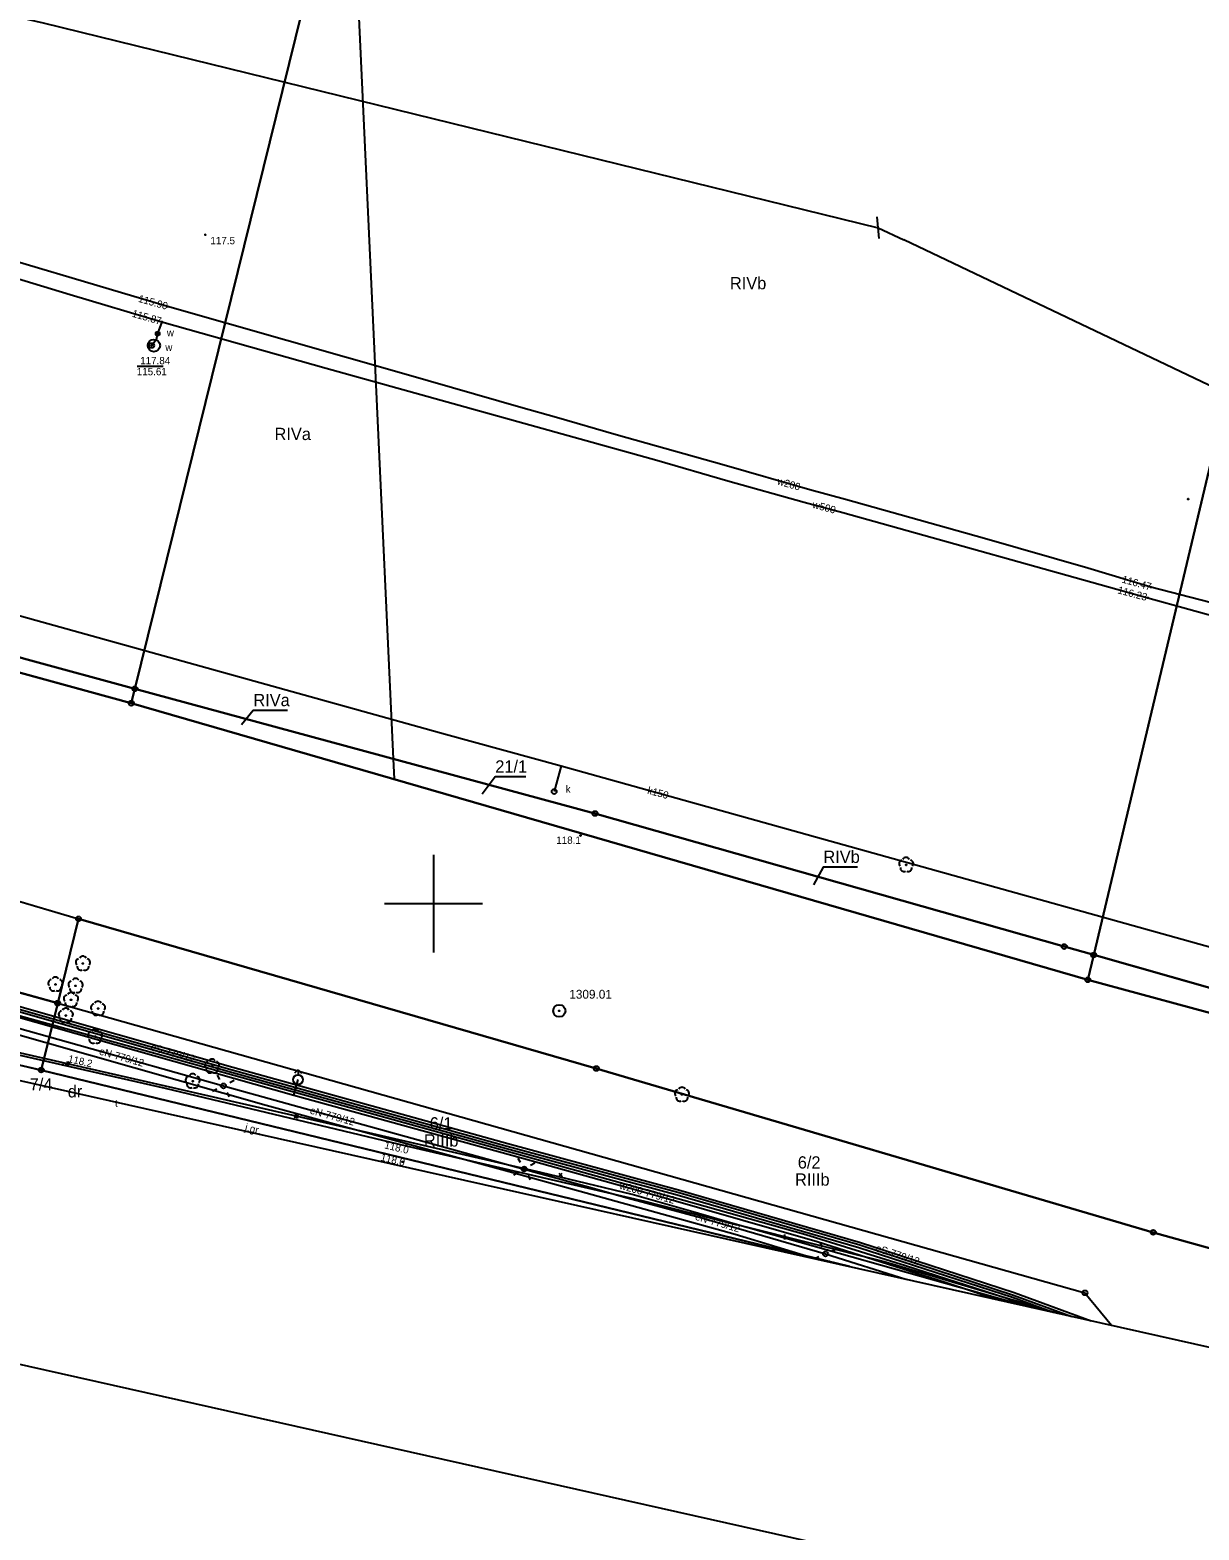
# Model space of a CAD drawing. Extents: x 6424617 to 6425697, y 5665845 to 5667190.
# Drawn here: x 6424958.8 to 6425078.2, y 5665936 to 5666089.2 of the extents above; entities that cross this region are included whole.
import ezdxf

# ---------------------------------------------------------------- set-up
doc = ezdxf.new("R2010")
doc.units = 0
for name, color, linetype in [('Warstwa 1', 7, 'Continuous'), ('Warstwa 10', 7, 'Continuous'), ('Warstwa 11', 7, 'Continuous'), ('Warstwa 12', 7, 'Continuous'), ('Warstwa 13', 7, 'Continuous'), ('Warstwa 14', 7, 'Continuous'), ('Warstwa 15', 7, 'Continuous'), ('Warstwa 16', 7, 'Continuous'), ('Warstwa 2', 7, 'Continuous'), ('Warstwa 21', 7, 'Continuous'), ('Warstwa 3', 7, 'Continuous'), ('Warstwa 4', 7, 'Continuous'), ('Warstwa 5', 7, 'Continuous'), ('Warstwa 6', 7, 'Continuous'), ('Warstwa 62', 7, 'Continuous'), ('Warstwa 63', 7, 'Continuous'), ('Warstwa 8', 7, 'Continuous')]:
    doc.layers.add(name, color=color, linetype=linetype)

msp = doc.modelspace()

# ---------------------------------------------------------------- linework, layer by layer
at = {"layer": 'Warstwa 1'}
for p, q in [((6425067.43, 5665994.76), (6425095.62, 5666113.43)), ((6425067.43, 5665994.76), (6425095.62, 5666113.43)), ((6424969.49, 5666021.95), (6424991.14, 5666109.69)), ((6424969.49, 5666021.95), (6424991.14, 5666109.69)), ((6424991.46, 5666109.7), (6424995.88, 5666014.79)), ((6424991.46, 5666109.7), (6424995.88, 5666014.79)), ((6424835.72, 5666057.05), (6424969.12, 5666020.47)), ((6424835.72, 5666057.05), (6424969.12, 5666020.47)), ((6424958.47, 5666024.93), (6424969.49, 5666021.95)), ((6424958.47, 5666024.93), (6424969.49, 5666021.95)), ((6424969.12, 5666020.47), (6424969.49, 5666021.95)), ((6424969.12, 5666020.47), (6424969.49, 5666021.95)), ((6424969.49, 5666021.95), (6424995.88, 5666014.79)), ((6424969.49, 5666021.95), (6424995.88, 5666014.79)), ((6424969.12, 5666020.47), (6424995.97, 5666012.71)), ((6424969.12, 5666020.47), (6425066.83, 5665992.22)), ((6424995.88, 5666014.79), (6424995.97, 5666012.71)), ((6424995.88, 5666014.79), (6425016.48, 5666009.21)), ((6424995.88, 5666014.79), (6424995.97, 5666012.71)), ((6424995.88, 5666014.79), (6425016.48, 5666009.21)), ((6424995.97, 5666012.71), (6425066.83, 5665992.22)), ((6424890.46, 5666009.6), (6424961.6, 5665989.83)), ((6424890.46, 5666009.6), (6424961.6, 5665989.83)), ((6425016.48, 5666009.21), (6425064.42, 5665995.62)), ((6425016.48, 5666009.21), (6425064.42, 5665995.62)), ((6424934.12, 5666007.2), (6424963.73, 5665998.45)), ((6424934.12, 5666007.2), (6424963.73, 5665998.45)), ((6424885.54, 5666000.14), (6424959.92, 5665983.01)), ((6424885.54, 5666000.14), (6424959.92, 5665983.01)), ((6424961.6, 5665989.83), (6424963.73, 5665998.45)), ((6424961.6, 5665989.83), (6424963.73, 5665998.45)), ((6424963.73, 5665998.45), (6425016.62, 5665983.17)), ((6424963.73, 5665998.45), (6425016.62, 5665983.17)), ((6425064.42, 5665995.62), (6425067.43, 5665994.76)), ((6425064.42, 5665995.62), (6425067.43, 5665994.76)), ((6425066.83, 5665992.22), (6425067.43, 5665994.76)), ((6425066.83, 5665992.22), (6425067.43, 5665994.76)), ((6425067.43, 5665994.76), (6425114.83, 5665981.3)), ((6425067.43, 5665994.76), (6425114.83, 5665981.3)), ((6425066.83, 5665992.22), (6425114.34, 5665979.37)), ((6425066.83, 5665992.22), (6425114.34, 5665979.37)), ((6424959.92, 5665983.01), (6424961.6, 5665989.83)), ((6424959.92, 5665983.01), (6424961.6, 5665989.83)), ((6424961.6, 5665989.83), (6425066.54, 5665960.25)), ((6424961.6, 5665989.83), (6425066.54, 5665960.25)), ((6424959.92, 5665983.01), (6425042.51, 5665962.94)), ((6424959.92, 5665983.01), (6425042.51, 5665962.94)), ((6425016.62, 5665983.17), (6425073.51, 5665966.43)), ((6425016.62, 5665983.17), (6425073.51, 5665966.43)), ((6425073.51, 5665966.43), (6425123.83, 5665952.42)), ((6425073.51, 5665966.43), (6425123.83, 5665952.42)), ((6425066.54, 5665960.25), (6425069.25, 5665956.94)), ((6425066.54, 5665960.25), (6425069.25, 5665956.94))]:
    msp.add_line(p, q, dxfattribs=at)
at = {"layer": 'Warstwa 10'}
msp.add_lwpolyline([(6425060.44, 5665958.92), (6425057.61, 5665959.71), (6425030.82, 5665967.28), (6425026.23, 5665968.58), (6425020.29, 5665970.3), (6425010.94, 5665972.53), (6424974.55, 5665980.91), (6424952.41, 5665985.97)], dxfattribs=at)
for centre in [(6424969.49, 5666021.95), (6424969.12, 5666020.47), (6424969.12, 5666020.47), (6425016.48, 5666009.21), (6424963.73, 5665998.45), (6425064.42, 5665995.62), (6425067.43, 5665994.76), (6425066.83, 5665992.22), (6425066.83, 5665992.22), (6424961.6, 5665989.83), (6424959.92, 5665983.01), (6425016.62, 5665983.17), (6425073.51, 5665966.43), (6425066.54, 5665960.25)]:
    msp.add_circle(centre, 0.25, dxfattribs=at)
at = {"layer": 'Warstwa 11'}
for centre in [(6425048.27, 5666003.96), (6424964.18, 5665993.89), (6424961.37, 5665991.76), (6424963.43, 5665991.61), (6424962.96, 5665990.18), (6424962.43, 5665988.57), (6424965.72, 5665989.28), (6424965.42, 5665986.43), (6424977.37, 5665983.39), (6424975.39, 5665981.87), (6425025.37, 5665980.51)]:
    msp.add_circle(centre, 0.05, dxfattribs=at)
for centre, start, end in [((6425047.92, 5666004.08), 102.1471, 221.8529), ((6425048.05, 5666003.66), 174.1471, 293.8529), ((6425048.27, 5666004.34), 30.1471, 149.8529), ((6425048.49, 5666003.66), 246.1471, 5.8529), ((6425048.63, 5666004.08), 318.1471, 77.8529), ((6424963.82, 5665994.01), 102.1471, 221.8529), ((6424964.18, 5665994.26), 30.1471, 149.8529), ((6424964.54, 5665994.01), 318.1471, 77.8529), ((6424963.96, 5665993.59), 174.1471, 293.8529), ((6424964.4, 5665993.59), 246.1471, 5.8529), ((6424961.01, 5665991.88), 102.1471, 221.8529), ((6424961.15, 5665991.46), 174.1471, 293.8529), ((6424961.37, 5665992.13), 30.1471, 149.8529), ((6424961.59, 5665991.46), 246.1471, 5.8529), ((6424961.73, 5665991.88), 318.1471, 77.8529), ((6424963.07, 5665991.73), 102.1471, 221.8529), ((6424963.21, 5665991.31), 174.1471, 293.8529), ((6424963.43, 5665991.99), 30.1471, 149.8529), ((6424963.65, 5665991.31), 246.1471, 5.8529), ((6424963.79, 5665991.73), 318.1471, 77.8529), ((6424962.6, 5665990.3), 102.1471, 221.8529), ((6424962.74, 5665989.88), 174.1471, 293.8529), ((6424962.96, 5665990.55), 30.1471, 149.8529), ((6424963.18, 5665989.88), 246.1471, 5.8529), ((6424963.32, 5665990.3), 318.1471, 77.8529), ((6424965.36, 5665989.4), 102.1471, 221.8529), ((6424965.72, 5665989.66), 30.1471, 149.8529), ((6424966.08, 5665989.4), 318.1471, 77.8529), ((6424962.07, 5665988.69), 102.1471, 221.8529), ((6424962.21, 5665988.27), 174.1471, 293.8529), ((6424962.43, 5665988.95), 30.1471, 149.8529), ((6424962.65, 5665988.27), 246.1471, 5.8529), ((6424962.79, 5665988.69), 318.1471, 77.8529), ((6424965.5, 5665988.98), 174.1471, 293.8529), ((6424965.94, 5665988.98), 246.1471, 5.8529), ((6424965.06, 5665986.55), 102.1471, 221.8529), ((6424965.42, 5665986.8), 30.1471, 149.8529), ((6424965.78, 5665986.55), 318.1471, 77.8529), ((6424965.2, 5665986.13), 174.1471, 293.8529), ((6424965.64, 5665986.13), 246.1471, 5.8529), ((6424977.01, 5665983.51), 102.1471, 221.8529), ((6424977.37, 5665983.76), 30.1471, 149.8529), ((6424977.73, 5665983.51), 318.1471, 77.8529), ((6424975.03, 5665981.99), 102.1471, 221.8529), ((6424975.39, 5665982.25), 30.1471, 149.8529), ((6424975.75, 5665981.99), 318.1471, 77.8529), ((6424977.15, 5665983.09), 174.1471, 293.8529), ((6424977.59, 5665983.09), 246.1471, 5.8529), ((6424975.17, 5665981.57), 174.1471, 293.8529), ((6424975.61, 5665981.57), 246.1471, 5.8529), ((6425025.01, 5665980.63), 102.1471, 221.8529), ((6425025.37, 5665980.88), 30.1471, 149.8529), ((6425025.73, 5665980.63), 318.1471, 77.8529), ((6425025.15, 5665980.21), 174.1471, 293.8529), ((6425025.59, 5665980.21), 246.1471, 5.8529)]:
    msp.add_arc(centre, 0.375, start, end, dxfattribs=at)
at = {"layer": 'Warstwa 12'}
for points in [[(6424940.11, 5666069.08), (6424943.78, 5666067.99), (6424962.88, 5666062.22), (6424972.24, 5666059.43), (6424989.04, 5666054.69), (6425022.79, 5666045.28), (6425030.07, 5666043.18), (6425037.86, 5666041), (6425041.81, 5666039.94), (6425072.97, 5666031.24), (6425127.39, 5666016.19)], [(6425192.87, 5665999.59), (6425180.06, 5666003.17), (6425173.22, 5666005.07), (6425118.59, 5666020.43), (6425101.46, 5666025.04), (6425073.28, 5666032.33), (6425066.83, 5666034.26), (6425056.27, 5666037.28), (6425042.06, 5666041.29), (6425038.43, 5666042.25), (6425029.69, 5666044.78), (6425018.65, 5666047.88), (6425012.55, 5666049.67), (6425008.91, 5666050.68), (6424997.2, 5666054.03), (6424972.82, 5666060.99), (6424949.85, 5666067.81), (6424945.63, 5666069.01)], [(6424972.24, 5666059.43), (6424971.81, 5666058.22), (6424971.67, 5666057.6), (6424971.2, 5666057.01)], [(6424902.19, 5666044.87), (6425001.23, 5666017.3), (6425013.02, 5666014.09), (6425115, 5665985.63), (6425128.06, 5665981.98), (6425136.27, 5665979.57), (6425176.94, 5665968.42), (6425209.55, 5665959.16), (6425214.47, 5665958.42), (6425209.55, 5665959.16)], [(6425013.02, 5666014.09), (6425012.31, 5666011.45)]]:
    msp.add_lwpolyline(points, dxfattribs=at)
at = {"layer": 'Warstwa 13'}
for centre in [(6424976.68, 5666068.32), (6425077.08, 5666041.32), (6425015, 5666006.95), (6424962.11, 5665983.54), (6424997.2, 5665975.28), (6424996.81, 5665973.63)]:
    msp.add_circle(centre, 0.045, dxfattribs=at)
at = {"layer": 'Warstwa 14'}
msp.add_line((6424972.37, 5666054.88), (6424969.72, 5666054.88), dxfattribs=at)
for centre in [(6424972.82, 5666060.99), (6424972.24, 5666059.43), (6424971.2, 5666057.01), (6425072.97, 5666031.24), (6425073.28, 5666032.33)]:
    msp.add_circle(centre, 0.045, dxfattribs=at)
at = {"layer": 'Warstwa 15'}
msp.add_lwpolyline([(6425009.41, 5666012.96), (6425006.29, 5666012.96), (6425004.97, 5666011.18)], dxfattribs=at)
at = {"layer": 'Warstwa 16'}
msp.add_circle((6424971.43, 5666057), 0.63, dxfattribs=at)
at = {"layer": 'Warstwa 2'}
for points in [[(6425045.5, 5666067.93), (6425045.3, 5666070.16)], [(6424985.07, 5666019.74), (6424981.58, 5666019.74), (6424980.36, 5666018.25)], [(6425043.29, 5666003.73), (6425039.81, 5666003.73), (6425038.79, 5666001.92)]]:
    msp.add_lwpolyline(points, dxfattribs=at)
at = {"layer": 'Warstwa 21'}
for points in [[(6424902.89, 5666103), (6424960.11, 5666089.96), (6425045.4, 5666069.04), (6425048.04, 5666067.79)], [(6425124.77, 5666031.22), (6425048.04, 5666067.79)]]:
    msp.add_lwpolyline(points, dxfattribs=at)
at = {"layer": 'Warstwa 3'}
for radius in [0.625, 0.045]:
    msp.add_circle((6425012.84, 5665989.06), radius, dxfattribs=at)
at = {"layer": 'Warstwa 4'}
for centre, radius in [((6424971.2, 5666057.01), 0.25), ((6424971.81, 5666058.22), 0.2), ((6424971.81, 5666058.22), 0.2), ((6425012.31, 5666011.45), 0.25)]:
    msp.add_circle(centre, radius, dxfattribs=at)
at = {"layer": 'Warstwa 6'}
for points in [[(6424969.49, 5666021.95), (6425016.48, 5666009.21), (6425064.42, 5665995.62), (6425067.43, 5665994.76), (6425095.62, 5666113.43), (6425096.29, 5666116.29), (6425115.39, 5666195.08), (6425119.56, 5666213.76), (6425122.85, 5666227.25), (6425131.54, 5666263.8), (6425125.72, 5666263.41), (6425105.79, 5666262.56), (6425075.81, 5666260.95), (6425039.49, 5666258.91), (6425034.31, 5666258.51), (6425027.97, 5666259.43), (6425019.26, 5666224.02), (6425014.82, 5666205.94), (6425010.77, 5666189.47), (6425000.54, 5666147.83), (6424995.09, 5666125.71)], [(6424995.09, 5666125.71), (6424929.13, 5666143.29), (6424860.07, 5666161.72), (6424858.37, 5666154.63), (6424848.43, 5666111.78), (6424836.07, 5666058.54), (6424900.68, 5666041.18), (6424958.47, 5666024.93), (6424969.49, 5666021.95)], [(6425067.43, 5665994.76), (6425114.83, 5665981.3), (6425147.52, 5666111.03), (6425137.6, 5666110.88), (6425095.62, 5666113.43)], [(6424900.68, 5666041.18), (6424836.07, 5666058.54), (6424835.72, 5666057.05), (6424969.12, 5666020.47), (6424969.49, 5666021.95), (6424958.47, 5666024.93)], [(6424860.2, 5666026.96), (6424894.39, 5666017.77), (6424934.12, 5666007.2), (6424963.73, 5665998.45), (6424961.6, 5665989.83), (6424858.78, 5666018.4)], [(6424969.49, 5666021.95), (6424969.12, 5666020.47), (6425066.83, 5665992.22), (6425067.43, 5665994.76), (6425064.42, 5665995.62), (6425016.48, 5666009.21)], [(6424858.78, 5666018.4), (6424961.6, 5665989.83), (6424959.92, 5665983.01), (6424856.84, 5666006.75)], [(6425067.43, 5665994.76), (6425066.83, 5665992.22), (6425114.34, 5665979.37), (6425114.83, 5665981.3)]]:
    msp.add_lwpolyline(points, close=True, dxfattribs=at)
for points in [[(6425247.92, 5665916.88), (6425244.9, 5665943.26), (6425213.05, 5665952.08), (6425191.26, 5665958.12), (6425175.28, 5665962.55), (6425160.35, 5665966.67), (6425114.34, 5665979.37), (6425066.83, 5665992.22), (6424969.12, 5666020.47), (6424835.72, 5666057.05), (6424831.92, 5666058.14), (6424794.14, 5666069.49), (6424779.33, 5666074.24), (6424752.27, 5666082.9), (6424722.03, 5666092.61), (6424673.98, 5666108.22), (6424664.2, 5666111.59)], [(6424658.97, 5666088.29), (6424687.91, 5666078.9), (6424716.67, 5666070.32), (6424715.7, 5666065.72), (6424712.33, 5666049.73), (6424785.75, 5666034.72), (6424788.43, 5666045.53), (6424790.34, 5666053.24), (6424828.33, 5666041.07), (6424860.53, 5666028.94), (6424934.12, 5666007.2), (6424963.73, 5665998.45), (6425016.62, 5665983.17), (6425073.51, 5665966.43), (6425123.83, 5665952.42), (6425122.41, 5665946.75), (6425151.64, 5665938.47)], [(6425042.51, 5665962.94), (6424959.92, 5665983.01), (6424856.84, 5666006.75), (6424825.41, 5666018.09), (6424784.69, 5666030.41), (6424784.21, 5666028.45), (6424710.62, 5666041.57), (6424651.3, 5666054.07)], [(6425122, 5665945.12), (6425122.41, 5665946.75), (6425123.83, 5665952.42), (6425073.51, 5665966.43), (6425016.62, 5665983.17), (6424963.73, 5665998.45), (6424961.6, 5665989.83), (6425066.54, 5665960.25), (6425069.25, 5665956.94)], [(6425042.51, 5665962.94), (6424959.92, 5665983.01), (6424961.6, 5665989.83), (6425066.54, 5665960.25), (6425069.25, 5665956.94)]]:
    msp.add_lwpolyline(points, dxfattribs=at)
at = {"layer": 'Warstwa 62'}
for p, q in [((6424926.46, 5665997.22), (6424969.92, 5665985.17)), ((6424947.68, 5665990.04), (6424963.78, 5665985.56)), ((6424951.76, 5665990.04), (6424985.73, 5665980.44)), ((6424955.77, 5665989.77), (6424979.42, 5665983.04)), ((6424955.84, 5665990.03), (6424979.49, 5665983.29)), ((6424955.7, 5665989.53), (6424979.35, 5665982.79)), ((6424955.87, 5665987.1), (6424982.88, 5665979.41)), ((6424963.78, 5665985.56), (6424978.53, 5665981.39)), ((6424969.92, 5665985.17), (6424994.63, 5665978.29)), ((6424979.35, 5665982.79), (6425007.43, 5665974.99)), ((6424979.42, 5665983.04), (6425007.5, 5665975.24)), ((6424979.49, 5665983.29), (6425007.57, 5665975.49)), ((6424986.15, 5665983.03), (6424985.8, 5665982.68)), ((6424986.15, 5665983.03), (6424986.15, 5665982.53)), ((6424986.15, 5665983.03), (6424986.51, 5665982.68)), ((6424978.53, 5665981.39), (6424996.2, 5665976.48)), ((6424985.73, 5665980.44), (6424986.15, 5665982.03)), ((6424982.88, 5665979.41), (6425008.09, 5665972.53)), ((6424985.73, 5665980.44), (6425008.98, 5665974.05)), ((6424994.63, 5665978.29), (6425025.55, 5665969.73)), ((6424996.2, 5665976.48), (6425009.25, 5665972.9)), ((6425007.43, 5665974.99), (6425024.89, 5665970.28)), ((6425007.5, 5665975.24), (6425024.96, 5665970.52)), ((6425007.57, 5665975.49), (6425025.03, 5665970.78)), ((6425008.98, 5665974.05), (6425023.98, 5665969.87)), ((6425009.25, 5665972.9), (6425015.83, 5665971.08)), ((6425008.09, 5665972.53), (6425030.81, 5665966.26)), ((6425015.83, 5665971.08), (6425019.78, 5665969.96)), ((6425019.78, 5665969.96), (6425027.4, 5665967.9)), ((6425023.98, 5665969.87), (6425039.19, 5665965.48)), ((6425024.89, 5665970.28), (6425043.45, 5665964.89)), ((6425024.96, 5665970.52), (6425043.53, 5665965.14)), ((6425025.03, 5665970.78), (6425043.6, 5665965.39)), ((6425025.55, 5665969.73), (6425038.01, 5665966.22)), ((6425027.4, 5665967.9), (6425040.04, 5665964.23)), ((6425030.81, 5665966.26), (6425039.33, 5665963.65)), ((6425038.01, 5665966.22), (6425048.19, 5665963.06)), ((6425039.19, 5665965.48), (6425052.27, 5665961.36)), ((6425043.6, 5665965.39), (6425059.31, 5665960.28)), ((6425040.04, 5665964.23), (6425048.25, 5665961.65)), ((6425043.45, 5665964.89), (6425059.14, 5665959.8)), ((6425043.53, 5665965.14), (6425059.22, 5665960.03)), ((6425048.19, 5665963.06), (6425058.57, 5665959.7)), ((6425052.27, 5665961.36), (6425057.83, 5665959.5)), ((6425058.57, 5665959.7), (6425061.16, 5665958.76)), ((6425059.14, 5665959.8), (6425063.29, 5665958.28)), ((6425059.22, 5665960.03), (6425065.2, 5665957.85)), ((6425059.31, 5665960.28), (6425067.16, 5665957.41))]:
    msp.add_line(p, q, dxfattribs=at)
for points in [[(6424962.38, 5665983.62), (6424962.87, 5665983.73)], [(6424962.57, 5665983.92), (6424962.68, 5665983.43)], [(6424978.17, 5665982.05), (6424977.93, 5665982.49)], [(6424977.87, 5665981.04), (6424977.43, 5665980.8)], [(6424978.89, 5665980.73), (6424979.13, 5665980.29)], [(6424979.19, 5665981.75), (6424979.63, 5665981.99)], [(6424985.76, 5665978.17), (6424986.21, 5665978.4)], [(6424985.87, 5665978.51), (6424986.1, 5665978.07)], [(6425008.88, 5665973.55), (6425008.63, 5665973.99)], [(6425009.9, 5665973.28), (6425010.33, 5665973.53)], [(6425008.6, 5665972.53), (6425008.17, 5665972.28)], [(6425009.62, 5665972.25), (6425009.87, 5665971.82)], [(6425012.79, 5665972.12), (6425013.14, 5665972.47)], [(6425012.79, 5665972.47), (6425013.14, 5665972.12)], [(6425035.58, 5665965.95), (6425036.08, 5665965.95)], [(6425035.83, 5665966.2), (6425035.83, 5665965.7)], [(6425039.73, 5665964.92), (6425039.52, 5665965.37)], [(6425039.36, 5665963.92), (6425038.95, 5665963.74)], [(6425040.72, 5665964.55), (6425041.18, 5665964.76)], [(6425040.35, 5665963.55), (6425040.42, 5665963.41)]]:
    msp.add_lwpolyline(points, dxfattribs=at)
for centre, radius in [((6424986.15, 5665982.03), 0.5), ((6424978.53, 5665981.39), 0.25), ((6425009.25, 5665972.9), 0.25), ((6425040.04, 5665964.23), 0.25)]:
    msp.add_circle(centre, radius, dxfattribs=at)
at = {"layer": 'Warstwa 63'}
for p, q in [((6425000, 5666005), (6425000, 5665995)), ((6425005, 5666000), (6424995, 5666000))]:
    msp.add_line(p, q, dxfattribs=at)
for points in [[(6424616.75, 5666029.38), (6424876.88, 5667189.58), (6425697.3, 5667005.64), (6425437.18, 5665845.44)], [(6425341.16, 5665895.98), (6425588.9, 5667000.93), (6424898.31, 5667155.76), (6424650.57, 5666050.81)]]:
    msp.add_lwpolyline(points, close=True, dxfattribs=at)
at = {"layer": 'Warstwa 8'}
for p, q in [((6424947.91, 5665986.77), (6424972.57, 5665981.16)), ((6424972.57, 5665981.16), (6424997.2, 5665975.28)), ((6424997.2, 5665975.28), (6425021.54, 5665969.6)), ((6425021.54, 5665969.6), (6425030.74, 5665967.28)), ((6425030.74, 5665967.28), (6425031.24, 5665967.16)), ((6425031.24, 5665967.16), (6425046.02, 5665963.44)), ((6425046.02, 5665963.44), (6425063.76, 5665958.17))]:
    msp.add_line(p, q, dxfattribs=at)

# ---------------------------------------------------------------- texts
at = {"layer": 'Warstwa 13'}
for s, p in [('117.5', (6424977.2, 5666067.35)), ('118.1', (6425012.53, 5666006.11))]:
    msp.add_text(s, height=0.75, dxfattribs=at).set_placement(p)
for s, rotation, p in [('w200', 343.832, (6425035.04, 5666042.84)), ('w500', 345.0524, (6425038.64, 5666040.44)), ('k150', 345.0409, (6425021.78, 5666011.24)), ('118.2', 347.1838, (6424962.6, 5665983.83)), ('118.0', 346.5707, (6424994.53, 5665973.77)), ('118.0', 346.5707, (6424994.92, 5665975.02))]:
    msp.add_text(s, height=0.75, rotation=rotation, dxfattribs=at).set_placement(p)
at = {"layer": 'Warstwa 14'}
for s, rotation, p in [('115.90', 344.2445, (6424969.77, 5666061.48)), ('115.87', 344.1127, (6424969.13, 5666059.96)), ('116.47', 344.4565, (6425070.25, 5666032.81)), ('116.23', 345.0753, (6425069.81, 5666031.71))]:
    msp.add_text(s, height=0.75, rotation=rotation, dxfattribs=at).set_placement(p)
msp.add_text('115.61', height=0.75, dxfattribs=at).set_placement((6424969.68, 5666053.97))
at = {"layer": 'Warstwa 15'}
for s, height, p in [('117.84', 0.75, (6424970.03, 5666055.09)), ('21/1', 1.25, (6425006.3, 5666013.39)), ('7/4', 1.25, (6424958.74, 5665980.92)), ('6/1', 1.25, (6424999.6, 5665976.94)), ('6/2', 1.25, (6425037.2, 5665972.95))]:
    msp.add_text(s, height=height, dxfattribs=at).set_placement(p)
at = {"layer": 'Warstwa 2'}
for s, p in [('RIVb', (6425030.27, 5666062.75)), ('RIVa', (6424983.75, 5666047.35)), ('RIVa', (6424981.59, 5666020.17)), ('RIVb', (6425039.82, 5666004.16)), ('dr', (6424962.63, 5665980.21)), ('RIIIb', (6424999.01, 5665975.19)), ('RIIIb', (6425036.92, 5665971.2))]:
    msp.add_text(s, height=1.25, dxfattribs=at).set_placement(p)
at = {"layer": 'Warstwa 4'}
msp.add_text('1309.01', height=0.9, dxfattribs=at).set_placement((6425013.86, 5665990.3))
at = {"layer": 'Warstwa 5'}
for s, p in [('w', (6424972.75, 5666057.94)), ('w', (6424972.75, 5666057.94)), ('w', (6424972.59, 5666056.46)), ('k', (6425013.49, 5666011.33)), ('t', (6424967.45, 5665979.25))]:
    msp.add_text(s, height=0.75, dxfattribs=at).set_placement(p)
at = {"layer": 'Warstwa 62'}
for s, rotation, p in [('eN-779/12', 344.2276, (6424965.78, 5665984.61)), ('eS-779/12', 344.1, (6424971.04, 5665985.03)), ('eN-779/12', 344.4729, (6424987.31, 5665978.57)), ('w200-779/12', 344.413, (6425018.93, 5665970.89)), ('eN-779/12', 343.8108, (6425026.66, 5665967.73)), ('eS-779/12', 341.9929, (6425045.09, 5665964.51))]:
    msp.add_text(s, height=0.75, rotation=rotation, dxfattribs=at).set_placement(p)
at = {"layer": 'Warstwa 8'}
msp.add_text('j.gr.', height=0.75, rotation=346.0837, dxfattribs=at).set_placement((6424980.68, 5665976.83))

doc.saveas('drawing.dxf')
